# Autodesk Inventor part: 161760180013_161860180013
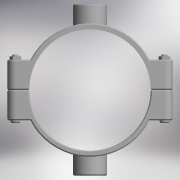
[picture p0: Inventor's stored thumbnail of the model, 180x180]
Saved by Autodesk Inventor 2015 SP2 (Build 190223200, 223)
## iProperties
Created: 2017-05
Part Number: 161760180013_161860180013
Material: Generic
Description: PLASSON DOUBLE SADDLE 180-1.1/4"
Document SubType Name: Modeling
Designer: KIM
Density: 1 g/cm^3
Appearance: Default
Author: KIM
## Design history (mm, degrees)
derived "16176.ipt"
feature "Solid1::16176.ipt"
feature "Solid2::16176.ipt"
tag "TaggingFeature1"
body "Solid1"
body "Solid2"
other parameters: "d0" = 198, "d1" = 245, "d4" = 154, "d5" = 0, "d6" = 12.25, "d7" = 245, "d8" = 0.1, "d10" = 0, "d11" = 1.8, "d20" = 1.8, "d23" = 1.8, "d36" = 15, "d37" = 12, "d38" = 98, "d39" = 0, "d40" = 3, "d41" = 5, "d42" = 0, "d44" = 3, "d45" = 0, "d46" = 1.8, "d52" = 38.952, "d53" = 25, "d54" = 0, "d55" = 32, "d57" = 0, "d58" = 194.4, "d60" = 0, "d62" = 15, "d63" = 12, "d67" = 254, "d68" = 50.6376, "d69" = 38.952, "d70" = 25, "d71" = 0, "d72" = 32, "d74" = 0, "d75" = 1.8, "B_" = 32, "G_" = 38.952, "A_" = 127, "L_" = 245, "L_1" = 154, "l_2" = 25
